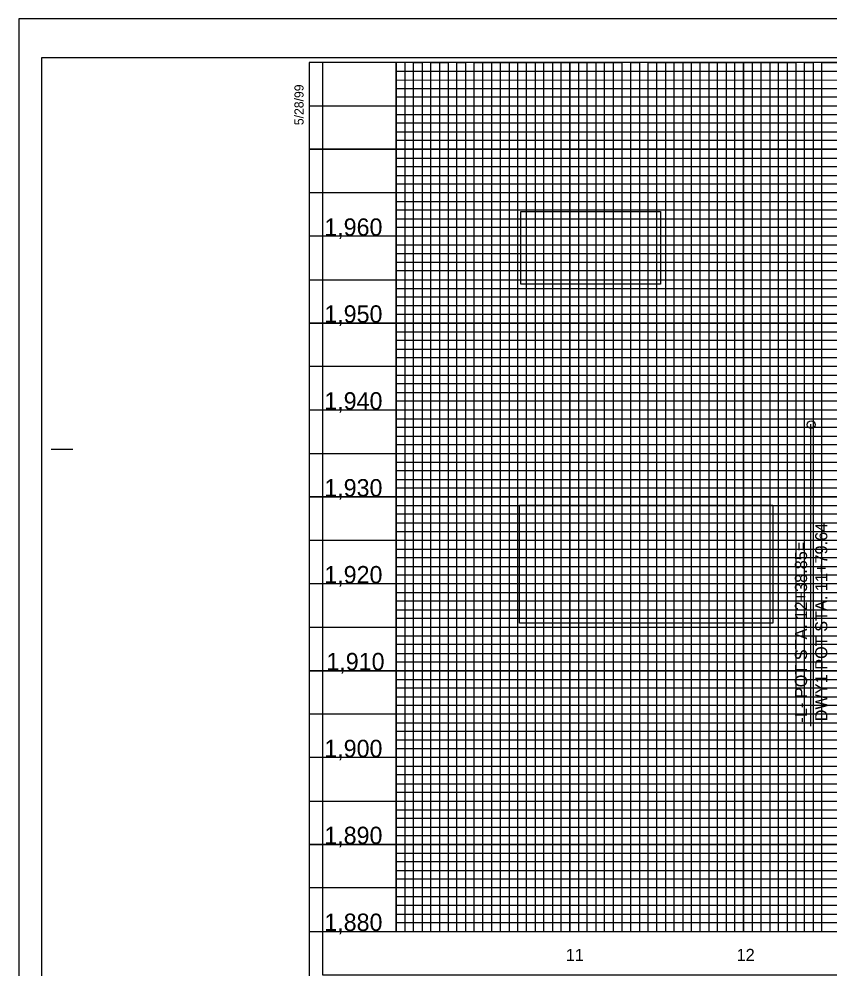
# Model space of a CAD drawing. Extents: x 557032 to 558716, y 513430 to 514605.
# Drawn here: x 557032 to 557499, y 513984 to 514530 of the extents above; entities that cross this region are included whole.
import ezdxf

# ---------------------------------------------------------------- set-up
doc = ezdxf.new("R2010")
doc.units = 0
for name, color, linetype in [('Exist Profile Cell', 7, 'Continuous'), ('Exist Vertical Profile Horizontal Axis Label Major', 7, 'Continuous'), ('Exist Vertical Profile Vertical Axis Label', 7, 'Continuous'), ('Prop Vertical Profile Curve Label', 7, 'Continuous'), ('Prop VPI Label', 7, 'Continuous'), ('Scratch_Level_5', 7, 'Continuous'), ('Sheet Cutting Line CELL', 7, 'Continuous'), ('Sheet DOT Grid CELL', 7, 'Continuous'), ('Sheet Layout Profile Border Port 1', 7, 'Continuous'), ('Sheet Plot Border Inside CELL', 7, 'Continuous'), ('Sheet Plot Border Outside CELL', 7, 'Continuous'), ('Sheet Profile CELL', 7, 'Continuous'), ('Sheet Profile Grid Major CELL', 7, 'Continuous'), ('Sheet Profile Grid Middle CELL', 7, 'Continuous'), ('Sheet Profile Grid Minor CELL', 7, 'Continuous')]:
    doc.layers.add(name, color=color, linetype=linetype)

msp = doc.modelspace()

# ---------------------------------------------------------------- linework, layer by layer
at = {"layer": 'Exist Profile Cell'}
msp.add_line((557249.45, 514007.64), (557249.45, 514488.82), dxfattribs=at)
at = {"layer": 'Prop Vertical Profile Curve Label'}
for points in [[(557321.26, 514419.68), (557401.68, 514419.68), (557401.68, 514377.87), (557321.26, 514377.87)], [(557320.4, 514250.71), (557466.23, 514250.71), (557466.23, 514182.85), (557320.4, 514182.85)]]:
    msp.add_lwpolyline(points, close=True, dxfattribs=at)
msp.add_circle((557488.33, 514296.94), 2.25, dxfattribs=at)
at = {"layer": 'Prop VPI Label'}
msp.add_line((557488.08, 514123.43), (557488.08, 514297.33), dxfattribs=at)
at = {"layer": 'Scratch_Level_5'}
msp.add_lwpolyline([(557207.08, 514505.4), (557207.08, 513980.4), (558649.45, 513980.4), (558649.45, 514344.35), (558499.4, 514344.35), (558499.4, 514505.4)], close=True, dxfattribs=at)
at = {"layer": 'Sheet Cutting Line CELL'}
for p, q in [((558716.45, 514530.4), (557032.45, 514530.4)), ((557032.45, 514530.4), (557032.45, 513430.4))]:
    msp.add_line(p, q, dxfattribs=at)
at = {"layer": 'Sheet DOT Grid CELL'}
for p, q in [((557249.45, 514005.4), (557249.45, 514505.4)), ((557299.45, 514005.4), (557299.45, 514505.4)), ((557349.45, 514005.4), (557349.45, 514505.4)), ((557399.45, 514005.4), (557399.45, 514505.4)), ((557449.45, 514005.4), (557449.45, 514505.4)), ((557249.45, 514007.64), (557249.45, 514488.82)), ((557299.45, 514011.48), (557299.45, 514488.82)), ((557349.45, 514011.45), (557349.45, 514488.82)), ((557399.45, 514011.41), (557399.45, 514488.82)), ((557449.45, 514011.37), (557449.45, 514488.82)), ((558499.4, 514455.4), (557199.45, 514455.4)), ((558484.51, 514455.4), (557203.74, 514455.4)), ((558499.4, 514405.4), (557199.45, 514405.4)), ((558484.51, 514405.4), (557203.83, 514405.4)), ((558499.45, 514355.4), (557199.45, 514355.4)), ((558484.51, 514355.4), (557203.92, 514355.4)), ((558699.45, 514305.4), (557199.45, 514305.4)), ((558693.5, 514305.4), (557204.01, 514305.4)), ((558699.45, 514255.4), (557199.45, 514255.4)), ((558693.5, 514255.4), (557204.1, 514255.4)), ((558699.45, 514205.4), (557199.45, 514205.4)), ((558693.5, 514205.4), (557204.18, 514205.4)), ((558699.45, 514155.4), (557199.45, 514155.4)), ((558693.5, 514155.4), (557204.27, 514155.4)), ((558699.45, 514105.4), (557199.45, 514105.4)), ((558693.5, 514105.4), (557204.36, 514105.4)), ((558699.45, 514055.4), (557199.45, 514055.4)), ((558693.5, 514055.4), (557204.45, 514055.4))]:
    msp.add_line(p, q, dxfattribs=at)
at = {"layer": 'Sheet Layout Profile Border Port 1'}
for points in [[(557249.45, 514344.35), (557249.45, 514005.4), (558649.45, 514005.4), (558649.45, 514344.35)], [(557249.45, 514344.35), (557249.45, 514007.64)]]:
    msp.add_lwpolyline(points, dxfattribs=at)
at = {"layer": 'Sheet Plot Border Inside CELL'}
msp.add_lwpolyline([(557045.45, 513452.85), (558711.95, 513452.85), (558711.95, 514507.95), (557045.45, 514507.95)], close=True, dxfattribs=at)
at = {"layer": 'Sheet Plot Border Outside CELL'}
msp.add_lwpolyline([(557032.45, 513430.4), (558716.45, 513430.4), (558716.45, 514530.4), (557032.45, 514530.4)], close=True, dxfattribs=at)
at = {"layer": 'Sheet Profile CELL'}
for p, q in [((557050.95, 514282.9), (557063.45, 514282.9)), ((557199.45, 514005.4), (558699.45, 514005.4)), ((557204.53, 514005.4), (557245.79, 514005.4))]:
    msp.add_line(p, q, dxfattribs=at)
msp.add_lwpolyline([(558699.45, 514505.4), (557199.45, 514505.4), (557199.45, 513455.4), (558699.45, 513455.4)], close=True, dxfattribs=at)
at = {"layer": 'Sheet Profile Grid Major CELL'}
for points in [[(557249.45, 514505.4), (557249.45, 514005.4), (557299.45, 514005.4), (557299.45, 514505.4), (557349.45, 514505.4), (557349.45, 514005.4), (557399.45, 514005.4), (557399.45, 514505.4), (557449.45, 514505.4), (557449.45, 514005.4), (557499.45, 514005.4)], [(557249.45, 514488.82), (557249.45, 514007.64)], [(557299.45, 514011.48), (557299.45, 514488.82)], [(557349.45, 514488.82), (557349.45, 514011.45)], [(557399.45, 514011.41), (557399.45, 514488.82)], [(557449.45, 514488.82), (557449.45, 514011.37)], [(557199.45, 514455.4), (558499.45, 514455.4)], [(557203.74, 514455.4), (558484.51, 514455.4)], [(558499.45, 514405.4), (557199.45, 514405.4), (557199.45, 514355.4), (558499.45, 514355.4)], [(558484.51, 514405.4), (557203.83, 514405.4)], [(557203.92, 514355.4), (558484.51, 514355.4)], [(558699.45, 514305.4), (557199.45, 514305.4), (557199.45, 514255.4), (558699.45, 514255.4)], [(558693.5, 514305.4), (557204.01, 514305.4)], [(557204.1, 514255.4), (558693.5, 514255.4)], [(558699.45, 514205.4), (557199.45, 514205.4), (557199.45, 514155.4), (558699.45, 514155.4)], [(558693.5, 514205.4), (557204.18, 514205.4)], [(557204.27, 514155.4), (558693.5, 514155.4)], [(558699.45, 514105.4), (557199.45, 514105.4), (557199.45, 514105.4), (557199.45, 514055.4), (558699.45, 514055.4)], [(558693.5, 514105.4), (557204.36, 514105.4)], [(557204.45, 514055.4), (558693.5, 514055.4)]]:
    msp.add_lwpolyline(points, dxfattribs=at)
at = {"layer": 'Sheet Profile Grid Middle CELL'}
for p, q in [((557199.45, 514480.4), (558499.4, 514480.4)), ((557203.7, 514480.4), (558484.51, 514480.4))]:
    msp.add_line(p, q, dxfattribs=at)
for points in [[(557274.45, 514505.4), (557274.45, 514005.4), (557324.45, 514005.4), (557324.45, 514505.4), (557374.45, 514505.4), (557374.45, 514005.4), (557424.45, 514005.4), (557424.45, 514505.4), (557474.45, 514505.4), (557474.45, 514005.4), (557524.45, 514005.4)], [(557274.45, 514488.82), (557274.45, 514011.5)], [(557324.45, 514011.47), (557324.45, 514488.82)], [(557374.45, 514488.82), (557374.45, 514011.43)], [(557424.45, 514011.39), (557424.45, 514488.82)], [(557474.45, 514488.82), (557474.45, 514011.36)], [(558499.45, 514430.4), (557199.45, 514430.4), (557199.45, 514380.4), (558499.45, 514380.4)], [(558484.51, 514430.4), (557203.79, 514430.4)], [(557203.88, 514380.4), (558484.51, 514380.4)], [(558699.45, 514330.4), (557199.45, 514330.4), (557199.45, 514280.4), (558524.45, 514280.4)], [(558484.51, 514330.4), (557203.96, 514330.4)], [(557204.05, 514280.4), (558524.45, 514280.4)], [(558699.45, 514230.4), (557199.45, 514230.4), (557199.45, 514180.4), (558699.45, 514180.4)], [(558693.5, 514230.4), (557204.14, 514230.4)], [(557204.23, 514180.4), (558693.5, 514180.4)], [(558699.45, 514130.4), (557199.45, 514130.4), (557199.45, 514080.4), (558699.45, 514080.4)], [(558693.5, 514130.4), (557204.32, 514130.4)], [(557204.4, 514080.4), (558693.5, 514080.4)], [(558699.45, 514030.4), (557199.45, 514030.4)], [(558444.08, 514030.4), (557204.49, 514030.4)]]:
    msp.add_lwpolyline(points, dxfattribs=at)
at = {"layer": 'Sheet Profile Grid Minor CELL'}
for p, q in [((557249.45, 514500.4), (558499.45, 514500.4)), ((557249.45, 514495.4), (557249.45, 514495.4)), ((558499.45, 514495.4), (557249.45, 514495.05)), ((557249.45, 514490.4), (558499.45, 514490.4)), ((558499.4, 514370.4), (557249.45, 514370.4)), ((558484.51, 514370.4), (557249.45, 514370.4)), ((558499.45, 514365.4), (557249.45, 514365.4)), ((558484.51, 514365.4), (557249.45, 514365.4)), ((558499.45, 514360.4), (557249.45, 514360.4)), ((558484.51, 514360.4), (557249.45, 514360.4)), ((557249.45, 514350.4), (558499.45, 514350.4)), ((557249.45, 514350.4), (558484.51, 514350.4)), ((558499.45, 514345.4), (557249.45, 514345.4)), ((558484.51, 514345.4), (557249.45, 514345.4)), ((557249.45, 514340.4), (558649.45, 514340.4)), ((557249.45, 514340.4), (558484.51, 514340.4)), ((558649.45, 514320.4), (557249.45, 514320.4)), ((558484.51, 514320.4), (557249.45, 514320.4)), ((557249.45, 514315.4), (558649.45, 514315.4)), ((557249.45, 514315.4), (558649.45, 514315.4)), ((558649.45, 514295.4), (557249.45, 514295.4)), ((558649.45, 514295.4), (557249.45, 514295.4)), ((557249.45, 514290.4), (558649.45, 514290.4)), ((557249.45, 514290.4), (558649.45, 514290.4)), ((558649.45, 514270.4), (557249.45, 514270.4)), ((558649.45, 514270.4), (557249.45, 514270.4)), ((557249.45, 514265.4), (558649.45, 514265.4)), ((557249.45, 514265.4), (558649.45, 514265.4)), ((558649.45, 514260.4), (557249.45, 514260.4)), ((558649.45, 514260.4), (557249.45, 514260.4)), ((557249.45, 514250.4), (558649.45, 514250.4)), ((557249.45, 514250.4), (558649.45, 514250.4)), ((558649.45, 514245.4), (557249.45, 514245.4)), ((558649.45, 514245.4), (557249.45, 514245.4)), ((557249.45, 514240.4), (558649.45, 514240.4)), ((557249.45, 514240.4), (558649.45, 514240.4)), ((558649.45, 514235.4), (557249.45, 514235.4)), ((558649.45, 514235.4), (557249.45, 514235.4)), ((557249.45, 514225.4), (558649.45, 514225.4)), ((557249.45, 514225.4), (558649.45, 514225.4)), ((558649.45, 514220.4), (557249.45, 514220.4)), ((558649.45, 514220.4), (557249.45, 514220.4)), ((557249.45, 514215.4), (558649.45, 514215.4)), ((557249.45, 514215.4), (558649.45, 514215.4)), ((558649.45, 514210.4), (557249.45, 514210.4)), ((558649.45, 514210.4), (557249.45, 514210.4)), ((557249.45, 514200.4), (558649.45, 514200.4)), ((557249.45, 514200.4), (558649.45, 514200.4)), ((558649.45, 514195.4), (557249.45, 514195.4)), ((558649.45, 514195.4), (557249.45, 514195.4)), ((557249.45, 514190.4), (558649.45, 514190.4)), ((557249.45, 514190.4), (558649.45, 514190.4)), ((558649.45, 514185.4), (557249.45, 514185.4)), ((558649.45, 514185.4), (557249.45, 514185.4)), ((557249.45, 514175.4), (558649.45, 514175.4)), ((557249.45, 514175.4), (558649.45, 514175.4)), ((558649.45, 514170.4), (557249.45, 514170.4)), ((558649.45, 514170.4), (557249.45, 514170.4)), ((557249.45, 514165.4), (558649.45, 514165.4)), ((557249.45, 514165.4), (558649.45, 514165.4)), ((558649.45, 514160.4), (557249.45, 514160.4)), ((558649.45, 514160.4), (557249.45, 514160.4)), ((557249.45, 514150.4), (558649.45, 514150.4)), ((557249.45, 514150.4), (558649.45, 514150.4)), ((558649.45, 514145.4), (557249.45, 514145.4)), ((558649.45, 514145.4), (557249.45, 514145.4)), ((557249.45, 514140.4), (558649.45, 514140.4)), ((557249.45, 514140.4), (558649.45, 514140.4)), ((558649.45, 514135.4), (557249.45, 514135.4)), ((558649.45, 514135.4), (557249.45, 514135.4)), ((557249.45, 514125.4), (558649.45, 514125.4)), ((557249.45, 514125.4), (558649.45, 514125.4)), ((558649.45, 514120.4), (557249.45, 514120.4)), ((558649.45, 514120.4), (557249.45, 514120.4)), ((558649.45, 514115.4), (557249.45, 514115.4)), ((558649.45, 514115.4), (557249.45, 514115.4)), ((558649.45, 514110.4), (557249.45, 514110.4)), ((558649.45, 514110.4), (557249.45, 514110.4)), ((557249.45, 514100.4), (558649.45, 514100.4)), ((557249.45, 514100.4), (558649.45, 514100.4)), ((558649.45, 514095.4), (557249.45, 514095.4)), ((558649.45, 514095.4), (557249.45, 514095.4)), ((557249.45, 514090.4), (558649.45, 514090.4)), ((557249.45, 514090.4), (558649.45, 514090.4)), ((558649.45, 514085.4), (557249.45, 514085.4)), ((558649.45, 514085.4), (557249.45, 514085.4)), ((557249.45, 514075.4), (558649.45, 514075.4)), ((557249.45, 514075.4), (558649.45, 514075.4)), ((558649.45, 514070.4), (557249.45, 514070.4)), ((558649.45, 514070.4), (557249.45, 514070.4)), ((557249.45, 514065.4), (558649.45, 514065.4)), ((557249.45, 514065.4), (558649.45, 514065.4)), ((558649.45, 514060.4), (557249.45, 514060.4)), ((558649.45, 514060.4), (557249.45, 514060.4)), ((557249.45, 514050.4), (558649.45, 514050.4)), ((557249.45, 514050.4), (558649.45, 514050.4)), ((558649.45, 514045.4), (557249.45, 514045.4)), ((558649.45, 514045.4), (557249.45, 514045.4)), ((557249.45, 514040.4), (558649.45, 514040.4)), ((557249.45, 514040.4), (558649.45, 514040.4)), ((558649.45, 514035.4), (557249.45, 514035.4)), ((558447.22, 514035.4), (557249.45, 514035.4)), ((557249.45, 514025.4), (558649.45, 514025.4)), ((557249.45, 514025.4), (558440.95, 514025.4)), ((558649.45, 514020.4), (557249.45, 514020.4)), ((558437.82, 514020.4), (557249.45, 514020.4)), ((557249.45, 514015.4), (558649.45, 514015.4)), ((557249.45, 514015.4), (558434.68, 514015.4))]:
    msp.add_line(p, q, dxfattribs=at)
for points in [[(557254.45, 514505.4), (557254.45, 514005.4), (557259.45, 514005.4), (557259.45, 514505.4), (557264.45, 514505.4), (557264.45, 514005.4), (557269.45, 514005.4), (557269.45, 514505.4), (557279.45, 514505.4), (557279.45, 514005.4), (557284.45, 514005.4), (557284.45, 514505.4), (557289.45, 514505.4), (557289.45, 514005.4), (557294.45, 514005.4), (557304.45, 514005.4), (557309.45, 514005.4), (557309.45, 514505.4), (557314.45, 514505.4), (557314.45, 514005.4), (557319.45, 514005.4), (557319.45, 514505.4), (557329.45, 514505.4), (557329.45, 514005.4), (557334.45, 514005.4), (557334.45, 514505.4), (557339.45, 514505.4), (557339.45, 514005.4), (557344.45, 514005.4), (557344.45, 514505.4), (557354.45, 514505.4), (557354.45, 514005.4), (557359.45, 514005.4), (557359.45, 514505.4), (557364.45, 514505.4), (557364.45, 514005.4), (557369.45, 514005.4), (557369.45, 514505.4), (557379.45, 514505.4), (557379.45, 514005.4), (557384.45, 514005.4), (557384.45, 514505.4), (557389.45, 514505.4), (557389.45, 514005.4), (557394.45, 514005.4), (557394.45, 514505.4), (557404.45, 514505.4), (557404.45, 514005.4), (557409.45, 514005.4), (557409.45, 514505.4), (557414.45, 514505.4), (557414.45, 514005.4), (557419.45, 514005.4), (557419.45, 514505.4), (557429.45, 514505.4), (557429.45, 514005.4), (557434.45, 514005.4), (557434.45, 514505.4), (557439.45, 514505.4), (557439.45, 514005.4), (557444.45, 514005.4), (557444.45, 514505.4), (557454.45, 514505.4), (557454.45, 514005.4), (557459.45, 514005.4), (557459.45, 514505.4), (557464.45, 514505.4), (557464.45, 514005.4)], [(557294.45, 514005.4), (557294.45, 514505.4), (557304.45, 514505.4), (557304.45, 514005.4)], [(557464.45, 514005.4), (557469.45, 514005.4), (557469.45, 514505.4), (557479.45, 514505.4), (557479.45, 514005.4), (557484.45, 514005.4), (557484.45, 514505.4), (557489.45, 514505.4), (557489.45, 514005.4), (557494.45, 514005.4), (557494.45, 514505.4), (557504.45, 514505.4)], [(558499.45, 514485.4), (557249.45, 514485.4), (557249.45, 514475.4), (558499.45, 514475.4)], [(558484.51, 514485.4), (557249.45, 514485.4), (557249.45, 514475.4), (558484.51, 514475.4)], [(557254.45, 514488.82), (557254.45, 514010.7)], [(557259.45, 514011.51), (557259.45, 514488.82)], [(557264.45, 514488.82), (557264.45, 514011.51)], [(557269.45, 514011.51), (557269.45, 514488.82)], [(557279.45, 514488.82), (557279.45, 514011.5)], [(557284.45, 514011.5), (557284.45, 514488.82)], [(557289.45, 514488.82), (557289.45, 514011.49)], [(557294.45, 514011.49), (557294.45, 514488.82)], [(557304.45, 514488.82), (557304.45, 514011.48)], [(557309.45, 514011.48), (557309.45, 514488.82)], [(557314.45, 514488.82), (557314.45, 514011.47)], [(557319.45, 514011.47), (557319.45, 514488.82)], [(557329.45, 514488.82), (557329.45, 514011.46)], [(557334.45, 514011.46), (557334.45, 514488.82)], [(557339.45, 514488.82), (557339.45, 514011.45)], [(557344.45, 514011.45), (557344.45, 514488.82)], [(557354.45, 514488.82), (557354.45, 514011.44)], [(557359.45, 514011.44), (557359.45, 514488.82)], [(557364.45, 514488.82), (557364.45, 514011.44)], [(557369.45, 514011.43), (557369.45, 514488.82)], [(557379.45, 514488.82), (557379.45, 514011.43)], [(557384.45, 514011.42), (557384.45, 514488.82)], [(557389.45, 514488.82), (557389.45, 514011.42)], [(557394.45, 514011.41), (557394.45, 514488.82)], [(557404.45, 514488.82), (557404.45, 514011.41)], [(557409.45, 514011.4), (557409.45, 514488.82)], [(557414.45, 514488.82), (557414.45, 514011.4)], [(557419.45, 514011.4), (557419.45, 514488.82)], [(557429.45, 514488.82), (557429.45, 514011.39)], [(557434.45, 514011.39), (557434.45, 514488.82)], [(557439.45, 514488.82), (557439.45, 514011.38)], [(557444.45, 514011.38), (557444.45, 514488.82)], [(557454.45, 514488.82), (557454.45, 514011.37)], [(557459.45, 514011.37), (557459.45, 514488.82)], [(557464.45, 514488.82), (557464.45, 514011.36)], [(557469.45, 514011.36), (557469.45, 514488.82)], [(557479.45, 514488.82), (557479.45, 514011.35)], [(557484.45, 514011.35), (557484.45, 514488.82)], [(557489.45, 514488.82), (557489.45, 514011.34)], [(557494.45, 514011.34), (557494.45, 514488.82)], [(558499.4, 514470.4), (557249.45, 514470.4), (557249.45, 514465.4), (558499.45, 514465.4)], [(558484.51, 514470.4), (557249.45, 514470.4), (557249.45, 514465.4), (558484.51, 514465.4)], [(558499.45, 514460.4), (557249.45, 514460.4), (557249.45, 514450.4), (558499.45, 514450.4)], [(558484.51, 514460.4), (557249.45, 514460.4), (557249.45, 514450.4), (558484.51, 514450.4)], [(558499.45, 514445.4), (557249.45, 514445.4), (557249.45, 514440.4), (558499.45, 514440.4)], [(558484.51, 514445.4), (557249.45, 514445.4), (557249.45, 514440.4), (558484.51, 514440.4)], [(558499.45, 514435.4), (557249.45, 514435.4), (557249.45, 514425.4), (558499.45, 514425.4)], [(558484.51, 514435.4), (557249.45, 514435.4), (557249.45, 514425.4), (558484.51, 514425.4)], [(558499.45, 514420.4), (557249.45, 514420.4), (557249.45, 514415.4), (558499.45, 514415.4)], [(558484.51, 514420.4), (557249.45, 514420.4), (557249.45, 514415.4), (558484.51, 514415.4)], [(558499.45, 514410.4), (557249.45, 514410.4), (557249.45, 514400.4), (558499.45, 514400.4)], [(558484.51, 514410.4), (557249.45, 514410.4), (557249.45, 514400.4), (558484.51, 514400.4)], [(558499.45, 514395.3), (557249.55, 514395.3), (557249.55, 514390.4), (558499.45, 514390.4)], [(558484.51, 514395.3), (557249.55, 514395.3), (557249.55, 514390.4), (558484.51, 514390.4)], [(558499.45, 514385.4), (557249.45, 514385.4), (557249.45, 514375.4), (558499.45, 514375.4)], [(558484.51, 514385.4), (557249.45, 514385.4), (557249.45, 514375.4), (558484.51, 514375.4)], [(558649.45, 514335.4), (557249.45, 514335.4), (557249.45, 514325.4), (558649.45, 514325.4)], [(558484.51, 514335.4), (557249.45, 514335.4), (557249.45, 514325.4), (558484.51, 514325.4)], [(558649.45, 514310.4), (557249.45, 514310.4), (557249.45, 514300.4), (558649.45, 514300.4)], [(558649.45, 514310.4), (557249.45, 514310.4), (557249.45, 514300.4), (558649.45, 514300.4)], [(558649.45, 514285.4), (557249.45, 514285.4), (557249.45, 514275.4), (558649.45, 514275.4)], [(558649.45, 514285.4), (557249.45, 514285.4), (557249.45, 514275.4), (558649.45, 514275.4)], [(558649.45, 514010.4), (557249.45, 514010.4)], [(557253.96, 514010.4), (557249.45, 514010.4)]]:
    msp.add_lwpolyline(points, dxfattribs=at)

# ---------------------------------------------------------------- texts
at = {"layer": 'Exist Vertical Profile Horizontal Axis Label Major'}
for s, p in [('11', (557347.14, 513988.37)), ('12', (557445.4, 513988.37))]:
    msp.add_text(s, height=7, dxfattribs=at).set_placement(p)
at = {"layer": 'Exist Vertical Profile Vertical Axis Label'}
for s, p in [('1,960', (557208.15, 514405.65)), ('1,960', (557208.15, 514405.65)), ('1,950', (557208.15, 514355.65)), ('1,950', (557208.15, 514355.65)), ('1,940', (557208.15, 514305.65)), ('1,940', (557208.15, 514305.65)), ('1,930', (557208.15, 514255.65)), ('1,930', (557208.15, 514255.65)), ('1,920', (557208.15, 514205.65)), ('1,920', (557208.15, 514205.65)), ('1,910', (557209.35, 514155.65)), ('1,910', (557209.35, 514155.65)), ('1,900', (557208.15, 514105.65)), ('1,900', (557208.15, 514105.65)), ('1,890', (557208.15, 514055.65)), ('1,890', (557208.15, 514055.65)), ('1,880', (557208.15, 514005.65)), ('1,880', (557208.15, 514005.65))]:
    msp.add_text(s, height=10, dxfattribs=at).set_placement(p)
at = {"layer": 'Prop VPI Label'}
for s, p in [('DWY1 POT STA. 11+79.64', (557497.61, 514126.3)), ('-L- POT STA. 12+38.85=', (557485.93, 514125.57))]:
    msp.add_text(s, height=7, rotation=90, dxfattribs=at).set_placement(p)
at = {"layer": 'Sheet Profile CELL'}
msp.add_text('5/28/99', height=5.25, rotation=90, dxfattribs=at).set_placement((557196.22, 514469.31))

doc.saveas('drawing.dxf')
